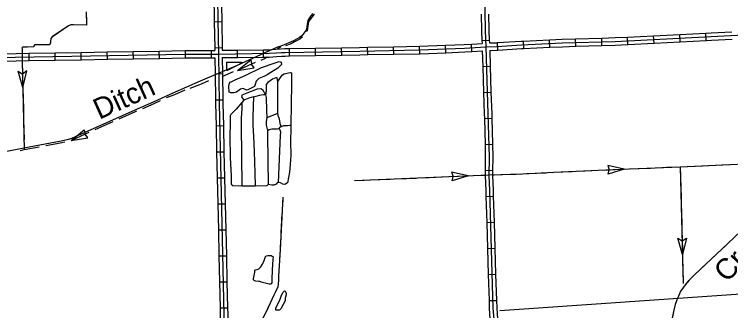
# Model space of a CAD drawing. Extents: x 1164457 to 1439835, y 1590918 to 1773502.
# Drawn here: x 1267982 to 1282506, y 1623464 to 1629475 of the extents above; entities that cross this region are included whole.
import ezdxf

# ---------------------------------------------------------------- set-up
doc = ezdxf.new("R2010")
doc.units = 0
for name, color, linetype in [('Level 32', 7, 'Continuous'), ('Level 35', 7, 'Continuous'), ('Level 43', 7, 'Continuous'), ('Level 5', 7, 'Continuous')]:
    doc.layers.add(name, color=color, linetype=linetype)

msp = doc.modelspace()

# ---------------------------------------------------------------- linework, layer by layer
at = {"layer": 'Level 32'}
for p, q in [((1272037, 1629326), (1272187, 1629328)), ((1279368, 1628828), (1279363, 1628978)), ((1279895, 1628844), (1279891, 1628994)), ((1280424, 1628865), (1280417, 1629015)), ((1280952, 1628891), (1280944, 1629041)), ((1281479, 1628917), (1281472, 1629067)), ((1282006, 1628943), (1281999, 1629093)), ((1276204, 1628677), (1276198, 1628827)), ((1276732, 1628697), (1276726, 1628847)), ((1277261, 1628722), (1277251, 1628871)), ((1277461, 1628946), (1277611, 1628953)), ((1277788, 1628751), (1277779, 1628901)), ((1278314, 1628783), (1278307, 1628933)), ((1278841, 1628807), (1278834, 1628957)), ((1268284, 1628536), (1268282, 1628686)), ((1268812, 1628545), (1268809, 1628695)), ((1269340, 1628554), (1269337, 1628704)), ((1269868, 1628563), (1269865, 1628713)), ((1270396, 1628572), (1270393, 1628722)), ((1270924, 1628581), (1270921, 1628731)), ((1271451, 1628590), (1271450, 1628740)), ((1271979, 1628594), (1271978, 1628744)), ((1272044, 1628798), (1272194, 1628800)), ((1272507, 1628600), (1272505, 1628750)), ((1273035, 1628607), (1273033, 1628757)), ((1273563, 1628630), (1273560, 1628780)), ((1274091, 1628639), (1274088, 1628789)), ((1274619, 1628648), (1274616, 1628798)), ((1275147, 1628658), (1275144, 1628808)), ((1275675, 1628667), (1275672, 1628817)), ((1277480, 1628420), (1277630, 1628424)), ((1272052, 1628270), (1272202, 1628272)), ((1277496, 1627892), (1277646, 1627896)), ((1272060, 1627742), (1272210, 1627744)), ((1277512, 1627365), (1277662, 1627368)), ((1272071, 1627214), (1272221, 1627217)), ((1277525, 1626837), (1277675, 1626840)), ((1272083, 1626686), (1272233, 1626689)), ((1277530, 1626311), (1277680, 1626310)), ((1272095, 1626158), (1272245, 1626161)), ((1277544, 1625781), (1277693, 1625785)), ((1272107, 1625630), (1272257, 1625633)), ((1277559, 1625253), (1277709, 1625257)), ((1272119, 1625102), (1272269, 1625106)), ((1277575, 1624725), (1277725, 1624730)), ((1272131, 1624574), (1272281, 1624578)), ((1277591, 1624197), (1277741, 1624202)), ((1272143, 1624046), (1272293, 1624050)), ((1277607, 1623670), (1277757, 1623674)), ((1272155, 1623519), (1272305, 1623522))]:
    msp.add_line(p, q, dxfattribs=at)
for points in [[(1271996, 1634077), (1272022, 1633288), (1272061, 1631361), (1272081, 1630906), (1272085, 1630603), (1272111, 1629377), (1272121, 1628670), (1272136, 1627664), (1272233, 1623389), (1272280, 1621173), (1272297, 1620719), (1272326, 1619394), (1272358, 1618084)], [(1277500, 1630748), (1277526, 1629144), (1277543, 1628816), (1277585, 1627456), (1277606, 1626578), (1277604, 1626205), (1277615, 1625899), (1277687, 1623516), (1277701, 1623292)], [(1272026, 1629853), (1272036, 1629376), (1272037, 1629326)], [(1272176, 1629856), (1272186, 1629378), (1272187, 1629328)], [(1277446, 1629476), (1277451, 1629141), (1277461, 1628946)], [(1277596, 1629478), (1277601, 1629146), (1277611, 1628953)], [(1272037, 1629326), (1272044, 1628798)], [(1272187, 1629328), (1272194, 1628800)], [(1281999, 1629093), (1282107, 1629098), (1282526, 1629121)], [(1266701, 1628614), (1266752, 1628602), (1266809, 1628597), (1266987, 1628595), (1267229, 1628593), (1271438, 1628665), (1272121, 1628670), (1273147, 1628684), (1273289, 1628692), (1273392, 1628702), (1273470, 1628704), (1274984, 1628730), (1276197, 1628752), (1277109, 1628787), (1277543, 1628816), (1277762, 1628825), (1278262, 1628856), (1279090, 1628894), (1280164, 1628927), (1282111, 1629023), (1282767, 1629059)], [(1278834, 1628957), (1279088, 1628969), (1279363, 1628978)], [(1279363, 1628978), (1279891, 1628994)], [(1279891, 1628994), (1280161, 1629002), (1280417, 1629015)], [(1280417, 1629015), (1280944, 1629041)], [(1280944, 1629041), (1281472, 1629067)], [(1281472, 1629067), (1281999, 1629093)], [(1282006, 1628943), (1282115, 1628948), (1282534, 1628971)], [(1275672, 1628817), (1276195, 1628827), (1276198, 1628827)], [(1276198, 1628827), (1276726, 1628847)], [(1276726, 1628847), (1277105, 1628862), (1277251, 1628871)], [(1277251, 1628871), (1277464, 1628886)], [(1277461, 1628946), (1277464, 1628886)], [(1277611, 1628953), (1277614, 1628894)], [(1277614, 1628894), (1277758, 1628900), (1277779, 1628901)], [(1277779, 1628901), (1278258, 1628930), (1278307, 1628933)], [(1278307, 1628933), (1278834, 1628957)], [(1278841, 1628807), (1279093, 1628819), (1279368, 1628828)], [(1279368, 1628828), (1279895, 1628844)], [(1279895, 1628844), (1280167, 1628852), (1280424, 1628865)], [(1280424, 1628865), (1280952, 1628891)], [(1280952, 1628891), (1281479, 1628917)], [(1281479, 1628917), (1282006, 1628943)], [(1267754, 1628677), (1268282, 1628686)], [(1268282, 1628686), (1268809, 1628695)], [(1268809, 1628695), (1269337, 1628704)], [(1269337, 1628704), (1269865, 1628713)], [(1269865, 1628713), (1270393, 1628722)], [(1270393, 1628722), (1270921, 1628731)], [(1270921, 1628731), (1271437, 1628740), (1271450, 1628740)], [(1271450, 1628740), (1271978, 1628744)], [(1271978, 1628744), (1272045, 1628744)], [(1272044, 1628798), (1272045, 1628744)], [(1272194, 1628800), (1272195, 1628746)], [(1272195, 1628746), (1272505, 1628750)], [(1272505, 1628750), (1273033, 1628757)], [(1273033, 1628757), (1273144, 1628758), (1273283, 1628767), (1273388, 1628777), (1273468, 1628779), (1273560, 1628780)], [(1273560, 1628780), (1274088, 1628789)], [(1274088, 1628789), (1274616, 1628798)], [(1274616, 1628798), (1274983, 1628805), (1275144, 1628808)], [(1275144, 1628808), (1275672, 1628817)], [(1275675, 1628667), (1276199, 1628677), (1276204, 1628677)], [(1276204, 1628677), (1276732, 1628697)], [(1276732, 1628697), (1277113, 1628712), (1277261, 1628722)], [(1277261, 1628722), (1277470, 1628736)], [(1277470, 1628736), (1277480, 1628420)], [(1277620, 1628744), (1277765, 1628750), (1277788, 1628751)], [(1277620, 1628744), (1277630, 1628424)], [(1277788, 1628751), (1278266, 1628781), (1278314, 1628783)], [(1278314, 1628783), (1278841, 1628807)], [(1267756, 1628527), (1268284, 1628536)], [(1268284, 1628536), (1268812, 1628545)], [(1268812, 1628545), (1269340, 1628554)], [(1269340, 1628554), (1269868, 1628563)], [(1269868, 1628563), (1270396, 1628572)], [(1270396, 1628572), (1270924, 1628581)], [(1270924, 1628581), (1271439, 1628590), (1271451, 1628590)], [(1271451, 1628590), (1271979, 1628594)], [(1271979, 1628594), (1272047, 1628594)], [(1272047, 1628594), (1272052, 1628270)], [(1272197, 1628596), (1272507, 1628600)], [(1272197, 1628596), (1272202, 1628272)], [(1272507, 1628600), (1273035, 1628607)], [(1273035, 1628607), (1273150, 1628609), (1273295, 1628617), (1273397, 1628627), (1273471, 1628629), (1273563, 1628630)], [(1273563, 1628630), (1274091, 1628639)], [(1274091, 1628639), (1274619, 1628648)], [(1274619, 1628648), (1274985, 1628655), (1275147, 1628658)], [(1275147, 1628658), (1275675, 1628667)], [(1277480, 1628420), (1277496, 1627892)], [(1277630, 1628424), (1277646, 1627896)], [(1272052, 1628270), (1272060, 1627742)], [(1272202, 1628272), (1272210, 1627744)], [(1277496, 1627892), (1277510, 1627454), (1277512, 1627365)], [(1277646, 1627896), (1277660, 1627458), (1277662, 1627368)], [(1272060, 1627742), (1272061, 1627663), (1272071, 1627214)], [(1272210, 1627744), (1272211, 1627666), (1272221, 1627217)], [(1277662, 1627368), (1277675, 1626840)], [(1277512, 1627365), (1277525, 1626837)], [(1272071, 1627214), (1272083, 1626686)], [(1272221, 1627217), (1272233, 1626689)], [(1277525, 1626837), (1277531, 1626577), (1277530, 1626311)], [(1277675, 1626840), (1277681, 1626578), (1277680, 1626310)], [(1272083, 1626686), (1272095, 1626158)], [(1272233, 1626689), (1272245, 1626161)], [(1277530, 1626311), (1277529, 1626204), (1277540, 1625896), (1277544, 1625781)], [(1277680, 1626310), (1277679, 1626206), (1277690, 1625901), (1277693, 1625785)], [(1272095, 1626158), (1272107, 1625630)], [(1272245, 1626161), (1272257, 1625633)], [(1277544, 1625781), (1277559, 1625253)], [(1277693, 1625785), (1277709, 1625257)], [(1272107, 1625630), (1272119, 1625102)], [(1272257, 1625633), (1272269, 1625106)], [(1277559, 1625253), (1277575, 1624725)], [(1277709, 1625257), (1277725, 1624730)], [(1272119, 1625102), (1272131, 1624574)], [(1272269, 1625106), (1272281, 1624578)], [(1277575, 1624725), (1277591, 1624197)], [(1277725, 1624730), (1277741, 1624202)], [(1272131, 1624574), (1272143, 1624046)], [(1272281, 1624578), (1272293, 1624050)], [(1277591, 1624197), (1277607, 1623670)], [(1277741, 1624202), (1277757, 1623674)], [(1272143, 1624046), (1272155, 1623519)], [(1272293, 1624050), (1272305, 1623522)], [(1277607, 1623670), (1277612, 1623513), (1277626, 1623289), (1277627, 1623228), (1277623, 1623178), (1277621, 1623152)], [(1277757, 1623674), (1277762, 1623520), (1277776, 1623294), (1277777, 1623223), (1277773, 1623165), (1277770, 1623138)], [(1272155, 1623519), (1272158, 1623388), (1272167, 1622991)], [(1272305, 1623522), (1272308, 1623391), (1272317, 1622994)]]:
    msp.add_lwpolyline(points, dxfattribs=at)
at = {"layer": 'Level 35'}
for points in [[(1272553, 1628463), (1272295, 1628336), (1272288, 1628334), (1272288, 1628443), (1272290, 1628504), (1272319, 1628506), (1272502, 1628506)], [(1272502, 1628506), (1272582, 1628508), (1272600, 1628497), (1272597, 1628482), (1272575, 1628475), (1272553, 1628463)], [(1272662, 1628231), (1272995, 1628395), (1273247, 1628486), (1273349, 1628521), (1273390, 1628506), (1273399, 1628456), (1273326, 1628381), (1273183, 1628294), (1273109, 1628249), (1273039, 1628211), (1272937, 1628175), (1272884, 1628120), (1272864, 1628055), (1272849, 1628014)], [(1273324, 1628114), (1273392, 1628217), (1273420, 1628249), (1273450, 1628270), (1273544, 1628289), (1273584, 1628296), (1273601, 1628291), (1273604, 1628259), (1273605, 1628068), (1273597, 1627649), (1273591, 1627225)], [(1272849, 1628014), (1272773, 1627970), (1272714, 1627941), (1272688, 1627935), (1272662, 1627947), (1272638, 1627965), (1272612, 1627968), (1272571, 1627959), (1272486, 1627897), (1272434, 1627881), (1272398, 1627885), (1272374, 1627885), (1272361, 1627887), (1272340, 1627899), (1272334, 1628020), (1272346, 1628077), (1272360, 1628096), (1272379, 1628109), (1272460, 1628143), (1272662, 1628231)], [(1273398, 1627202), (1273377, 1627236), (1273360, 1627347), (1273333, 1627426), (1273327, 1627467), (1273327, 1627526), (1273324, 1628114), (1273313, 1628185), (1273281, 1628189), (1273219, 1628161), (1273125, 1628094), (1273090, 1628053), (1273085, 1628009), (1273090, 1627915), (1273073, 1627840)], [(1272602, 1627839), (1272704, 1627880), (1272909, 1627965), (1272982, 1627971), (1273011, 1627948), (1273073, 1627840)], [(1272602, 1627839), (1272591, 1627801), (1272637, 1627737)], [(1272833, 1627802), (1272985, 1627845), (1273032, 1627851), (1273058, 1627851), (1273073, 1627840), (1273085, 1627790), (1273096, 1627526), (1273099, 1627374), (1273087, 1627301), (1273087, 1627224), (1273099, 1627172), (1273114, 1627122), (1273114, 1627017), (1273128, 1626025)], [(1272833, 1627802), (1272736, 1627772), (1272637, 1627737), (1272596, 1627687), (1272480, 1627552), (1272370, 1627446), (1272356, 1627415), (1272359, 1627245), (1272350, 1627008), (1272359, 1626566), (1272376, 1626203), (1272379, 1626028), (1272409, 1626001), (1272596, 1625998), (1272868, 1625998), (1273108, 1626004), (1273128, 1626025)], [(1272596, 1627687), (1272596, 1627567), (1272581, 1627368), (1272578, 1627219), (1272596, 1625998)], [(1272833, 1627802), (1272821, 1627401), (1272821, 1627228), (1272830, 1626997), (1272848, 1626695), (1272856, 1626259), (1272868, 1625998)], [(1273327, 1627467), (1273286, 1627453), (1273137, 1627388), (1273099, 1627374)], [(1273114, 1627122), (1273149, 1627137), (1273204, 1627152), (1273316, 1627155), (1273354, 1627161), (1273374, 1627184), (1273398, 1627202), (1273444, 1627222), (1273521, 1627222), (1273570, 1627225), (1273591, 1627225), (1273591, 1627175), (1273582, 1626891), (1273585, 1626616), (1273573, 1626432), (1273561, 1626271), (1273521, 1626060), (1273465, 1626022), (1273424, 1626028), (1273380, 1626054), (1273333, 1626063), (1273313, 1626057), (1273289, 1626031), (1273245, 1626007), (1273204, 1626013), (1273128, 1626025)], [(1273354, 1627161), (1273365, 1627131), (1273377, 1627090), (1273371, 1627014), (1273333, 1626063)], [(1272982, 1624353), (1273011, 1624407), (1273048, 1624482), (1273070, 1624540), (1273078, 1624560), (1273090, 1624574), (1273124, 1624582), (1273164, 1624584), (1273192, 1624584), (1273207, 1624573), (1273224, 1624564), (1273231, 1624554), (1273226, 1624502), (1273212, 1624296)], [(1273212, 1624296), (1273203, 1624097), (1273204, 1624055), (1273200, 1624030), (1273192, 1624007), (1273173, 1624005), (1273150, 1624005), (1272985, 1624042), (1272977, 1624052), (1272963, 1624058), (1272938, 1624058), (1272877, 1624066), (1272861, 1624067), (1272844, 1624075), (1272833, 1624090), (1272833, 1624107), (1272856, 1624248), (1272858, 1624270), (1272875, 1624291), (1272903, 1624299), (1272938, 1624310), (1272962, 1624332), (1272982, 1624353)], [(1273342, 1623637), (1273370, 1623700), (1273401, 1623776), (1273432, 1623843), (1273463, 1623867), (1273470, 1623863), (1273481, 1623844), (1273495, 1623812), (1273495, 1623788), (1273478, 1623739), (1273473, 1623722), (1273473, 1623700), (1273470, 1623663)], [(1273470, 1623663), (1273436, 1623592), (1273385, 1623505), (1273367, 1623479), (1273353, 1623476), (1273331, 1623476), (1273299, 1623476), (1273286, 1623478), (1273282, 1623491), (1273283, 1623519), (1273342, 1623637)]]:
    msp.add_lwpolyline(points, dxfattribs=at)
at = {"layer": 'Level 43'}
for p, q in [((1272506, 1628336), (1272775, 1628555)), ((1272775, 1628555), (1272788, 1628465)), ((1272506, 1628336), (1272844, 1628393)), ((1272844, 1628393), (1272788, 1628465)), ((1269134, 1626916), (1269401, 1627133)), ((1269401, 1627133), (1269415, 1627042)), ((1269134, 1626916), (1269473, 1626970)), ((1269473, 1626970), (1269416, 1627041)), ((1280349, 1626335), (1280015, 1626411)), ((1280015, 1626411), (1280042, 1626323)), ((1277184, 1626199), (1276849, 1626274)), ((1276849, 1626274), (1276877, 1626187)), ((1280349, 1626335), (1280022, 1626233)), ((1280022, 1626233), (1280042, 1626322)), ((1277184, 1626199), (1276857, 1626097)), ((1276857, 1626097), (1276877, 1626186))]:
    msp.add_line(p, q, dxfattribs=at)
for points in [[(1274036, 1629489), (1273994, 1629444), (1273968, 1629405), (1273938, 1629363), (1273928, 1629313), (1273905, 1629174), (1273890, 1629144), (1273808, 1629041), (1273763, 1629005), (1273718, 1628981), (1273655, 1628947), (1273582, 1628908), (1273455, 1628859), (1273384, 1628832), (1273318, 1628810), (1273137, 1628731), (1272498, 1628438), (1272116, 1628275), (1271752, 1628119), (1271196, 1627877), (1270797, 1627694), (1270422, 1627528), (1269144, 1626958), (1269081, 1626938), (1268931, 1626900), (1268174, 1626758), (1266758, 1626480)], [(1269442, 1629526), (1269444, 1629258), (1269178, 1629265), (1269127, 1629263), (1269078, 1629244), (1268751, 1629017), (1268722, 1628987), (1268711, 1628868), (1268690, 1628856), (1268394, 1628858), (1268377, 1628816), (1268150, 1628809), (1268135, 1628798), (1268138, 1628784), (1268141, 1628683), (1268142, 1628533)], [(1269443, 1629419), (1269444, 1629258), (1269209, 1629264)], [(1274065, 1629474), (1274047, 1629457), (1274005, 1629412), (1273979, 1629373), (1273949, 1629331), (1273939, 1629281), (1273916, 1629142), (1273907, 1629124)], [(1269081, 1629245), (1269078, 1629244), (1268755, 1629020)], [(1273828, 1629020), (1273819, 1629009), (1273774, 1628972), (1273729, 1628949), (1273665, 1628915), (1273593, 1628876), (1273482, 1628833)], [(1268714, 1628902), (1268711, 1628868), (1268690, 1628856), (1268394, 1628858), (1268378, 1628820)], [(1268249, 1628812), (1268150, 1628809), (1268135, 1628798), (1268138, 1628784), (1268141, 1628683)], [(1273387, 1628813), (1273317, 1628770)], [(1268142, 1628533), (1268185, 1626726)], [(1273107, 1628608), (1273070, 1628579), (1272979, 1628537)], [(1268145, 1628388), (1268150, 1628190)], [(1272866, 1628501), (1272506, 1628336)], [(1268155, 1627992), (1268058, 1628321), (1268148, 1628263)], [(1268155, 1627992), (1268236, 1628326), (1268148, 1628263)], [(1272420, 1628308), (1272203, 1628215)], [(1268150, 1628190), (1268155, 1627992)], [(1271917, 1628123), (1271771, 1628060), (1271735, 1628045)], [(1271735, 1628045), (1271542, 1627969)], [(1268158, 1627860), (1268168, 1627464)], [(1271441, 1627934), (1271229, 1627845), (1271062, 1627778)], [(1270942, 1627723), (1270808, 1627661), (1270581, 1627561)], [(1270460, 1627508), (1270433, 1627496), (1270099, 1627347)], [(1268171, 1627332), (1268180, 1626936)], [(1269978, 1627293), (1269616, 1627132)], [(1269496, 1627078), (1269154, 1626925), (1269133, 1626919)], [(1268183, 1626804), (1268185, 1626726)], [(1268812, 1626843), (1268618, 1626807)], [(1269006, 1626884), (1268942, 1626868), (1268812, 1626843)], [(1268488, 1626783), (1268185, 1626726), (1268099, 1626709)], [(1274876, 1626103), (1277605, 1626217), (1278154, 1626234), (1278921, 1626271), (1280270, 1626332), (1280808, 1626353), (1281485, 1626385), (1283067, 1626456), (1284107, 1626509), (1284206, 1626494)], [(1280481, 1626340), (1280808, 1626353), (1280877, 1626356)], [(1281009, 1626362), (1281207, 1626372)], [(1284206, 1626494), (1282448, 1624827), (1281771, 1624193), (1281662, 1624084), (1281581, 1623988), (1281551, 1623943), (1281517, 1623896), (1281491, 1623857), (1281467, 1623805), (1281446, 1623760), (1281431, 1623716), (1281409, 1623666), (1281383, 1623591), (1281354, 1623477), (1281191, 1622676)], [(1281207, 1626372), (1281404, 1626381)], [(1281485, 1626385), (1281932, 1626405)], [(1281485, 1626385), (1281543, 1624016)], [(1281485, 1626385), (1281490, 1626187)], [(1282064, 1626411), (1282459, 1626429)], [(1277316, 1626205), (1277529, 1626213)], [(1277679, 1626219), (1277712, 1626220)], [(1277844, 1626224), (1278042, 1626231)], [(1278042, 1626231), (1278154, 1626234), (1278240, 1626238)], [(1278371, 1626245), (1278767, 1626263)], [(1278899, 1626269), (1278921, 1626271), (1279294, 1626287)], [(1279426, 1626293), (1279822, 1626311)], [(1279954, 1626317), (1280270, 1626332), (1280349, 1626335)], [(1274876, 1626103), (1275074, 1626111)], [(1275206, 1626116), (1275602, 1626133)], [(1275734, 1626138), (1276129, 1626155)], [(1276261, 1626161), (1276657, 1626177)], [(1276789, 1626183), (1277184, 1626199)], [(1281493, 1626055), (1281503, 1625659)], [(1273427, 1625768), (1273369, 1624697), (1273340, 1624158), (1273338, 1624081), (1273332, 1624008), (1273323, 1623938), (1273299, 1623894), (1273279, 1623849), (1273242, 1623781), (1273126, 1623529), (1272794, 1622836), (1272576, 1622375), (1272502, 1622200), (1272422, 1622059), (1272368, 1621979), (1272311, 1621906), (1272264, 1621868), (1272186, 1621801), (1271874, 1621464), (1271184, 1620774), (1270944, 1620547)], [(1273427, 1625768), (1273416, 1625570)], [(1281506, 1625527), (1281516, 1625131)], [(1273409, 1625438), (1273388, 1625043)], [(1273381, 1624911), (1273369, 1624697), (1273359, 1624516)], [(1281528, 1624603), (1281435, 1624934), (1281522, 1624879)], [(1281519, 1624999), (1281528, 1624603)], [(1281522, 1624879), (1281611, 1624936), (1281528, 1624603)], [(1282411, 1624793), (1282122, 1624522)], [(1281532, 1624471), (1281541, 1624076)], [(1273352, 1624384), (1273340, 1624158), (1273338, 1624081), (1273332, 1624008), (1273329, 1623989)], [(1282026, 1624432), (1281771, 1624193), (1281738, 1624160)], [(1281646, 1624065), (1281581, 1623988), (1281551, 1623943), (1281517, 1623896), (1281491, 1623857), (1281467, 1623805), (1281446, 1623760), (1281436, 1623732)], [(1273286, 1623866), (1273279, 1623849), (1273242, 1623781), (1273126, 1623529), (1273116, 1623508)], [(1281389, 1623609), (1281383, 1623591), (1281354, 1623477), (1281302, 1623223)]]:
    msp.add_lwpolyline(points, dxfattribs=at)
at = {"layer": 'Level 5'}
msp.add_lwpolyline([(1277826, 1623466), (1282911, 1623821)], dxfattribs=at)

# ---------------------------------------------------------------- texts
at = {"layer": 'Level 35'}
msp.add_text('Creek', height=422.4, rotation=47.2456, dxfattribs=at).set_placement((1282435, 1624019))
at = {"layer": 'Level 43'}
msp.add_text('Ditch', height=422.4, rotation=24.3596, dxfattribs=at).set_placement((1269704, 1627334))

doc.saveas('drawing.dxf')
